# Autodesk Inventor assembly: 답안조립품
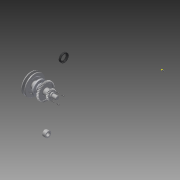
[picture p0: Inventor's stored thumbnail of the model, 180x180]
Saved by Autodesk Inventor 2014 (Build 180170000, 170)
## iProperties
Created: 2016-01
Part Number: 답안조립품
Document SubType Name: Assembly
Designer: USER
Author: USER
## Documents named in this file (16)
- C:\Users\USER\Desktop\460105V1031\답안조립품.iam
- C:\Users\USER\Desktop\460105V1031\본체.ipt
- C:\Users\USER\Desktop\460105V1031\부시2.ipt
- C:\Users\USER\Desktop\460105V1031\스퍼기어.ipt
- C:\Users\USER\Desktop\460105V1031\앞커버.ipt
- C:\Users\USER\Desktop\460105V1031\오일씰 28 40 8.ipt
- C:\Users\USER\Desktop\460105V1031\축.ipt
- C:\Users\USER\Desktop\460105V1031\키 - 5 x 5 x 18.ipt
- C:\Users\USER\Desktop\460105V1031\키 - 6 x 6 x 22.ipt
- C:\Users\USER\Desktop\460105V1031\V-벨트풀리.ipt
- C:\Users\USER\Desktop\460105V1031\뒤커버.ipt
- C:\Users\USER\Desktop\460105V1031\멈춤나사 - M4x10.ipt
- C:\Users\USER\Desktop\460105V1031\베어링 6203.ipt
- C:\Users\USER\Desktop\460105V1031\볼트 M3 x 8.ipt
- C:\Users\USER\Desktop\460105V1031\볼트 M3 x 10.ipt
- C:\Users\USER\Desktop\460105V1031\부시1.ipt
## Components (9 placed, 3 different names)
1. V-벨트풀리:1
2. ISO 4762 M3 x 8:1
3. ISO 4762 M3 x 8:2
4. ISO 4762 M3 x 8:3
5. ISO 4762 M3 x 8:4
6. ISO 4762 M3 x 10:1
7. ISO 4762 M3 x 10:2
8. ISO 4762 M3 x 10:3
9. ISO 4762 M3 x 10:4
